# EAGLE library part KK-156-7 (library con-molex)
KK 156 HEADER Source: http://www.molex.com/pdm_docs/sd/026604100_sd.pdf
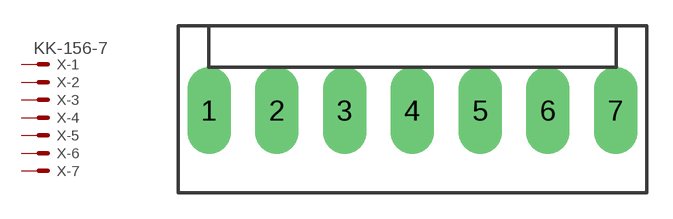
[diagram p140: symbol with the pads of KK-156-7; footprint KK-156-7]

Designator prefix X; gates -1=MV -2=M -3=M -4=M -5=M -6=M -7=M

## KK-156-7 (OC_FARNELL: unknown; OC_NEWARK: unknown)  [KK-156-7]
1  -1:S  pas
2  -2:S  pas
3  -3:S  pas
4  -4:S  pas
5  -5:S  pas
6  -6:S  pas
7  -7:S  pas

## Footprint KK-156-7 (pad centres in mm)
KK 156 HEADER Source: http://www.molex.com/pdm_docs/sd/026604100_sd.pdf
drill 1.7 pad 2.184 long: 1 -11.88,0; 2 -7.92,0; 3 -3.96,0; 4 0,0; 5 3.96,0; 6 7.92,0; 7 11.88,0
